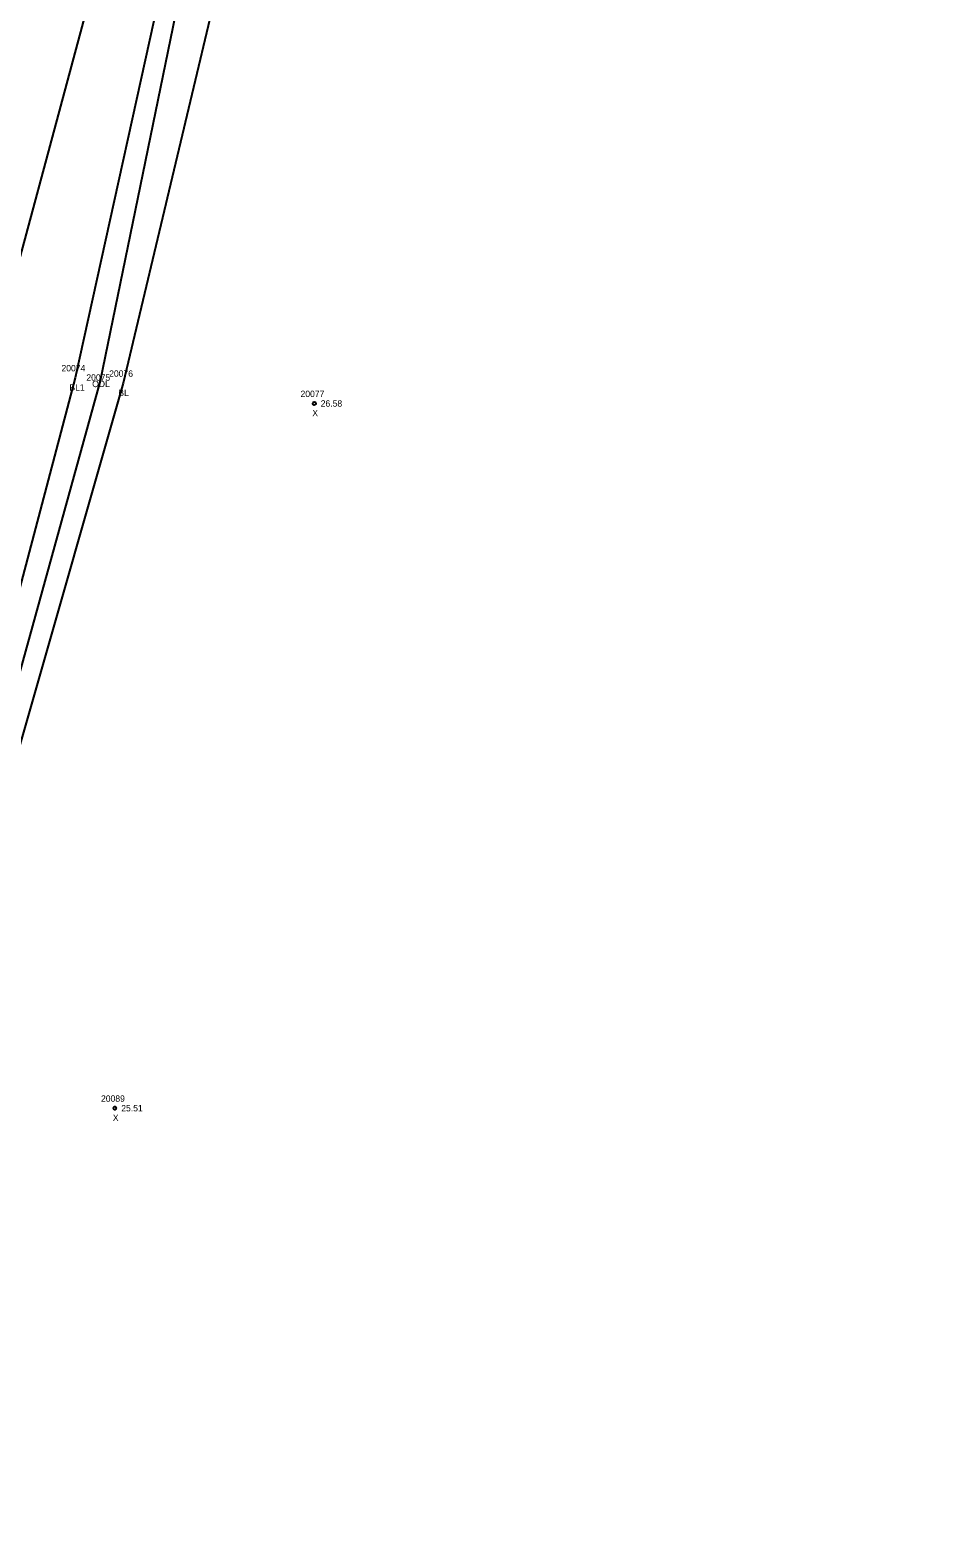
# Model space of a CAD drawing. Extents: x 2432729 to 2433340, y 684958 to 688103.
# Drawn here: x 2433020.9 to 2433161.1, y 687397.5 to 687632.9 of the extents above; entities that cross this region are included whole.
import ezdxf

# ---------------------------------------------------------------- set-up
doc = ezdxf.new("R2010")
doc.units = 0
for name, color, linetype in [('RD_DTM_BkLn1', 7, 'Continuous'), ('RD_EX_H2O', 7, 'Continuous'), ('RD_EX_H2O_txCode', 7, 'Continuous'), ('RD_EX_Road', 7, 'Continuous'), ('RD_Sketch8', 7, 'Continuous'), ('RD_SMD_Locator', 7, 'Continuous'), ('RD_SMD_Misc', 7, 'Continuous')]:
    doc.layers.add(name, color=color, linetype=linetype)

msp = doc.modelspace()

# ---------------------------------------------------------------- linework, layer by layer
at = {"layer": 'RD_DTM_BkLn1'}
for points in [[(2433156.54, 688084.3), (2433128.42, 687980.72), (2433101.84, 687880.23), (2433076.15, 687783.58), (2433056.79, 687706.65), (2433053.61, 687680.85), (2433043.6, 687649.71), (2433027.96, 687578.58), (2432999.4, 687470.47), (2432976.82, 687380.76), (2432967.08, 687327.52), (2432956.82, 687270.44), (2432953.12, 687234.52), (2432952.13, 687211.69)], [(2433161.14, 688083.06), (2433133.45, 687979.3), (2433106.44, 687878.75), (2433080.34, 687782.58), (2433063.71, 687704.97), (2433062.78, 687678.91), (2433051.75, 687646.46), (2433035.42, 687577.73), (2433004.6, 687469.86), (2432982.67, 687378.73), (2432971.98, 687326.06), (2432962.83, 687268.71), (2432961.78, 687241.18), (2432987.4, 687248.62)]]:
    msp.add_lwpolyline(points, dxfattribs=at)
at = {"layer": 'RD_EX_H2O'}
msp.add_lwpolyline([(2433158.82, 688083.82), (2433130.6, 687980.05), (2433103.89, 687879.65), (2433077.93, 687783.05), (2433058.91, 687706.24), (2433056.32, 687679.85), (2433046.3, 687648.55), (2433031.84, 687578.12), (2433002.04, 687470.32), (2432979.46, 687380.11), (2432969.67, 687326.76), (2432959.16, 687269.46), (2432956.03, 687234.5)], dxfattribs=at)
at = {"layer": 'RD_EX_Road'}
msp.add_lwpolyline([(2433151.11, 688085.43), (2433123.35, 687982.08), (2433096.36, 687882.07), (2433070.62, 687785.25), (2433042.64, 687684.31), (2433015.24, 687582.49), (2432986.34, 687474.01), (2432964, 687384.38), (2432952.4, 687330.76), (2432943.09, 687273.42), (2432937.12, 687213.43), (2432935.51, 687158.7)], dxfattribs=at)
at = {"layer": 'RD_SMD_Locator'}
for centre, radius in [((2433027.96, 687578.58), 0.001), ((2433031.84, 687578.12), 0.001), ((2433035.42, 687577.73), 0.001), ((2433065.25, 687574.57), 0.25), ((2433034.13, 687464.54), 0.25)]:
    msp.add_circle(centre, radius, dxfattribs=at)

# ---------------------------------------------------------------- texts
at = {"layer": 'RD_EX_H2O_txCode'}
for s, p in [('20075', (2433029.68, 687578.12)), ('ODL', (2433030.59, 687577.12))]:
    msp.add_text(s, height=1, dxfattribs=at).set_placement(p)
at = {"layer": 'RD_Sketch8'}
for s, p in [('20077', (2433063.1, 687575.57)), ('26.58', (2433066.25, 687574.07)), ('X', (2433064.94, 687572.57)), ('20089', (2433031.97, 687465.54)), ('X', (2433033.81, 687462.54)), ('25.51', (2433035.13, 687464.04))]:
    msp.add_text(s, height=1, dxfattribs=at).set_placement(p)
at = {"layer": 'RD_SMD_Misc'}
for s, p in [('20074', (2433025.8, 687579.58)), ('20076', (2433033.24, 687578.73)), ('BL1', (2433027.04, 687576.58)), ('BL', (2433034.67, 687575.73))]:
    msp.add_text(s, height=1, dxfattribs=at).set_placement(p)

doc.saveas('drawing.dxf')
